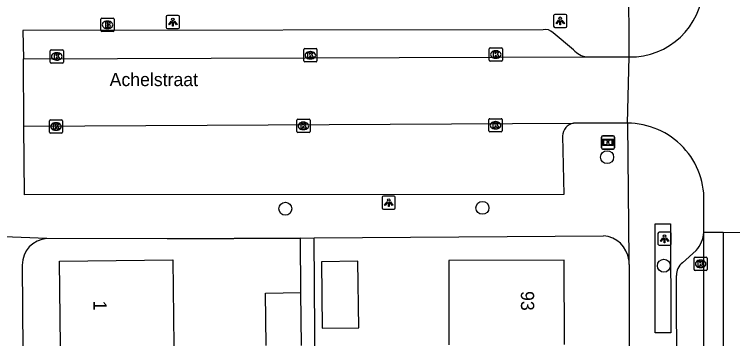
# Model space of a CAD drawing. Extents: x 160732 to 162105, y 387428 to 388479.
# Drawn here: x 161248.1 to 161302.4, y 388250.9 to 388275.4 of the extents above; entities that cross this region are included whole.
import ezdxf

# ---------------------------------------------------------------- set-up
doc = ezdxf.new("R2010")
doc.units = 0
for name, color, linetype in [('IMGEO_Boom', 7, 'Continuous'), ('IMGEO_Brandkraan', 7, 'Continuous'), ('IMGEO_Informatiebord', 7, 'Continuous'), ('IMGEO_Kolk', 7, 'Continuous'), ('IMGEO_Lichtpunt', 7, 'Continuous'), ('IMGEO_Muur', 7, 'Continuous'), ('IMGEO_Openbare_ruimte_label', 7, 'Continuous'), ('IMGEO_Pand', 7, 'Continuous'), ('IMGEO_Pand_nummerreeks', 7, 'Continuous'), ('IMGEO_Rijbaan_lokaal_gesloten', 7, 'Continuous'), ('IMGEO_Rijbaan_lokaal_open', 7, 'Continuous'), ('IMGEO_Voetpad_open', 7, 'Continuous')]:
    doc.layers.add(name, color=color, linetype=linetype)

msp = doc.modelspace()

# ---------------------------------------------------------------- linework, layer by layer
at = {"layer": 'IMGEO_Boom'}
for centre in [(161292.915, 388264.627), (161268.574, 388260.723), (161283.483, 388260.792), (161297.209, 388256.413)]:
    msp.add_circle(centre, 0.489, dxfattribs=at)
at = {"layer": 'IMGEO_Brandkraan'}
for p, q in [((161254.615, 388274.211), (161254.615, 388275.063)), ((161254.69, 388275.137), (161255.542, 388275.137)), ((161255.103, 388274.917), (161255.128, 388274.917)), ((161255.616, 388275.063), (161255.616, 388274.211)), ((161255.126, 388274.357), (161255.101, 388274.357)), ((161255.542, 388274.137), (161254.69, 388274.137))]:
    msp.add_line(p, q, dxfattribs=at)
for points in [[(161254.615, 388274.211), (161254.615, 388275.063)], [(161254.69, 388275.137), (161255.542, 388275.137)], [(161255.616, 388275.063), (161255.616, 388274.211)], [(161254.963, 388274.837), (161254.963, 388274.437), (161255.176, 388274.437)], [(161255.194, 388274.837), (161254.963, 388274.837)], [(161255.142, 388274.756), (161255.088, 388274.756), (161255.088, 388274.68)], [(161255.088, 388274.68), (161255.141, 388274.68)], [(161255.15, 388274.604), (161255.088, 388274.604), (161255.088, 388274.523)], [(161255.088, 388274.523), (161255.15, 388274.523)], [(161255.542, 388274.137), (161254.69, 388274.137)]]:
    msp.add_lwpolyline(points, dxfattribs=at)
for centre, radius, start, end in [((161254.692, 388275.061), 0.0765, 91.552, 178.448), ((161254.692, 388275.061), 0.0765, 91.552, 178.448), ((161255.54, 388275.061), 0.0765, 1.552, 88.448), ((161255.54, 388275.061), 0.0765, 1.552, 88.448), ((161255.143, 388274.718), 0.0379, 267.8285, 90.9355), ((161255.151, 388274.563), 0.0404, 269.8759, 90.5077), ((161255.182, 388274.688), 0.251, 268.6676, 293.5347), ((161255.198, 388274.692), 0.145, 59.4692, 91.5367), ((161255.223, 388274.739), 0.0922, 285.5137, 58.1501), ((161255.228, 388274.547), 0.105, 301.3115, 78.989), ((161254.692, 388274.213), 0.0765, 181.552, 268.448), ((161254.692, 388274.213), 0.0765, 181.552, 268.448), ((161255.54, 388274.213), 0.0765, 271.552, 358.448), ((161255.54, 388274.213), 0.0765, 271.552, 358.448)]:
    msp.add_arc(centre, radius, start, end, dxfattribs=at)
for centre, major_axis, ratio, start_param, end_param in [((161255.102, 388274.637), (-0.387, 0.002), 0.722429, 4.712389, 7.853982), ((161255.127, 388274.637), (-0.39, 0.002), 0.717154, 1.570796, 4.712389)]:
    msp.add_ellipse(centre, major_axis=major_axis, ratio=ratio, start_param=start_param, end_param=end_param, dxfattribs=at)
at = {"layer": 'IMGEO_Informatiebord'}
for p, q in [((161292.586, 388266.244), (161293.376, 388266.244)), ((161293.376, 388266.244), (161292.586, 388266.244)), ((161292.486, 388265.344), (161292.486, 388266.144)), ((161292.486, 388266.144), (161292.486, 388265.344)), ((161293.476, 388266.144), (161293.476, 388265.344)), ((161293.476, 388265.344), (161293.476, 388266.144)), ((161293.376, 388265.244), (161292.586, 388265.244)), ((161292.586, 388265.244), (161293.376, 388265.244))]:
    msp.add_line(p, q, dxfattribs=at)
for points in [[(161292.587, 388265.976), (161293.375, 388265.976), (161293.375, 388265.512), (161292.587, 388265.512), (161292.587, 388265.976)], [(161292.652, 388265.911), (161292.652, 388265.577), (161292.927, 388265.577), (161292.928, 388265.79), (161293.032, 388265.791), (161293.033, 388265.577), (161293.31, 388265.577), (161293.31, 388265.911), (161293.034, 388265.911), (161293.034, 388265.831), (161292.928, 388265.831), (161292.928, 388265.911), (161292.652, 388265.911)]]:
    msp.add_lwpolyline(points, dxfattribs=at)
for centre, start, end in [((161292.586, 388266.144), 90, 180), ((161292.586, 388266.144), 90, 180), ((161293.376, 388266.144), 0, 90), ((161293.376, 388266.144), 360, 90), ((161292.586, 388265.344), 180, 270), ((161292.586, 388265.344), 180, 270), ((161293.376, 388265.344), 270, 0), ((161293.376, 388265.344), 270, 0)]:
    msp.add_arc(centre, 0.1, start, end, dxfattribs=at)
at = {"layer": 'IMGEO_Kolk'}
for p, q in [((161250.853, 388272.746), (161251.705, 388272.746)), ((161269.964, 388271.909), (161269.964, 388272.761)), ((161270.039, 388272.835), (161270.891, 388272.835)), ((161270.965, 388272.761), (161270.965, 388271.909)), ((161283.995, 388271.963), (161283.995, 388272.815)), ((161284.07, 388272.889), (161284.922, 388272.889)), ((161284.996, 388272.815), (161284.996, 388271.963)), ((161250.778, 388271.82), (161250.778, 388272.672)), ((161251.266, 388272.526), (161251.291, 388272.526)), ((161251.779, 388272.672), (161251.779, 388271.82)), ((161270.452, 388272.615), (161270.477, 388272.615)), ((161284.483, 388272.669), (161284.508, 388272.669)), ((161251.705, 388271.746), (161250.853, 388271.746)), ((161251.289, 388271.966), (161251.264, 388271.966)), ((161270.891, 388271.835), (161270.039, 388271.835)), ((161270.475, 388272.055), (161270.45, 388272.055)), ((161284.922, 388271.889), (161284.07, 388271.889)), ((161284.506, 388272.109), (161284.481, 388272.109)), ((161250.719, 388266.519), (161250.719, 388267.371)), ((161250.794, 388267.445), (161251.646, 388267.445)), ((161251.72, 388267.371), (161251.72, 388266.519)), ((161269.438, 388266.566), (161269.438, 388267.418)), ((161269.513, 388267.492), (161270.365, 388267.492)), ((161269.926, 388267.272), (161269.951, 388267.272)), ((161270.439, 388267.418), (161270.439, 388266.566)), ((161283.976, 388266.612), (161283.976, 388267.464)), ((161284.051, 388267.538), (161284.903, 388267.538)), ((161284.464, 388267.318), (161284.489, 388267.318)), ((161284.977, 388267.464), (161284.977, 388266.612)), ((161251.207, 388267.225), (161251.232, 388267.225)), ((161284.487, 388266.758), (161284.462, 388266.758)), ((161251.646, 388266.445), (161250.794, 388266.445)), ((161251.23, 388266.665), (161251.205, 388266.665)), ((161270.365, 388266.492), (161269.513, 388266.492)), ((161269.949, 388266.712), (161269.924, 388266.712)), ((161284.903, 388266.538), (161284.051, 388266.538)), ((161299.491, 388256.129), (161299.491, 388256.981)), ((161299.566, 388257.055), (161300.418, 388257.055)), ((161300.492, 388256.981), (161300.492, 388256.129)), ((161299.979, 388256.835), (161300.004, 388256.835)), ((161300.418, 388256.055), (161299.566, 388256.055)), ((161300.002, 388256.275), (161299.977, 388256.275))]:
    msp.add_line(p, q, dxfattribs=at)
for points in [[(161250.853, 388272.746), (161251.705, 388272.746)], [(161269.964, 388271.909), (161269.964, 388272.761)], [(161270.039, 388272.835), (161270.891, 388272.835)], [(161270.965, 388272.761), (161270.965, 388271.909)], [(161283.995, 388271.963), (161283.995, 388272.815)], [(161284.07, 388272.889), (161284.922, 388272.889)], [(161284.996, 388272.815), (161284.996, 388271.963)], [(161250.778, 388271.82), (161250.778, 388272.672)], [(161251.099, 388272.446), (161251.222, 388272.446), (161251.222, 388272.295), (161251.352, 388272.446), (161251.516, 388272.446), (161251.37, 388272.295), (161251.523, 388272.046), (161251.371, 388272.046), (161251.286, 388272.21), (161251.222, 388272.143), (161251.222, 388272.046), (161251.099, 388272.046), (161251.099, 388272.446)], [(161251.779, 388272.672), (161251.779, 388271.82)], [(161270.285, 388272.535), (161270.408, 388272.535), (161270.408, 388272.384), (161270.538, 388272.535), (161270.702, 388272.535), (161270.556, 388272.384), (161270.709, 388272.135), (161270.557, 388272.135), (161270.472, 388272.299), (161270.408, 388272.232), (161270.408, 388272.135), (161270.285, 388272.135), (161270.285, 388272.535)], [(161284.316, 388272.589), (161284.439, 388272.589), (161284.439, 388272.438), (161284.569, 388272.589), (161284.733, 388272.589), (161284.587, 388272.438), (161284.74, 388272.189), (161284.588, 388272.189), (161284.503, 388272.353), (161284.439, 388272.286), (161284.439, 388272.189), (161284.316, 388272.189), (161284.316, 388272.589)], [(161251.705, 388271.746), (161250.853, 388271.746)], [(161270.891, 388271.835), (161270.039, 388271.835)], [(161284.922, 388271.889), (161284.07, 388271.889)], [(161250.719, 388266.519), (161250.719, 388267.371)], [(161250.794, 388267.445), (161251.646, 388267.445)], [(161251.72, 388267.371), (161251.72, 388266.519)], [(161269.438, 388266.566), (161269.438, 388267.418)], [(161269.513, 388267.492), (161270.365, 388267.492)], [(161270.439, 388267.418), (161270.439, 388266.566)], [(161283.976, 388266.612), (161283.976, 388267.464)], [(161284.051, 388267.538), (161284.903, 388267.538)], [(161284.977, 388267.464), (161284.977, 388266.612)], [(161251.04, 388267.145), (161251.163, 388267.145), (161251.163, 388266.994), (161251.293, 388267.145), (161251.457, 388267.145), (161251.311, 388266.994), (161251.464, 388266.745), (161251.312, 388266.745), (161251.227, 388266.909), (161251.163, 388266.842), (161251.163, 388266.745), (161251.04, 388266.745), (161251.04, 388267.145)], [(161269.759, 388267.192), (161269.882, 388267.192), (161269.882, 388267.041), (161270.012, 388267.192), (161270.176, 388267.192), (161270.03, 388267.041), (161270.183, 388266.792), (161270.031, 388266.792), (161269.946, 388266.956), (161269.882, 388266.889), (161269.882, 388266.792), (161269.759, 388266.792), (161269.759, 388267.192)], [(161284.297, 388267.238), (161284.42, 388267.238), (161284.42, 388267.087), (161284.55, 388267.238), (161284.714, 388267.238), (161284.568, 388267.087), (161284.721, 388266.838), (161284.569, 388266.838), (161284.484, 388267.002), (161284.42, 388266.935), (161284.42, 388266.838), (161284.297, 388266.838), (161284.297, 388267.238)], [(161251.646, 388266.445), (161250.794, 388266.445)], [(161270.365, 388266.492), (161269.513, 388266.492)], [(161284.903, 388266.538), (161284.051, 388266.538)], [(161299.491, 388256.129), (161299.491, 388256.981)], [(161299.566, 388257.055), (161300.418, 388257.055)], [(161300.492, 388256.981), (161300.492, 388256.129)], [(161299.812, 388256.755), (161299.935, 388256.755), (161299.935, 388256.604), (161300.065, 388256.755), (161300.229, 388256.755), (161300.083, 388256.604), (161300.236, 388256.355), (161300.084, 388256.355), (161299.999, 388256.519), (161299.935, 388256.452), (161299.935, 388256.355), (161299.812, 388256.355), (161299.812, 388256.755)], [(161300.418, 388256.055), (161299.566, 388256.055)]]:
    msp.add_lwpolyline(points, dxfattribs=at)
for centre, start, end in [((161250.855, 388272.67), 91.552, 178.448), ((161250.855, 388272.67), 91.552, 178.448), ((161251.703, 388272.67), 1.552, 88.448), ((161251.703, 388272.67), 1.552, 88.448), ((161270.041, 388272.759), 91.552, 178.448), ((161270.041, 388272.759), 91.552, 178.448), ((161270.889, 388272.759), 1.552, 88.448), ((161270.889, 388272.759), 1.552, 88.448), ((161284.072, 388272.813), 91.552, 178.448), ((161284.072, 388272.813), 91.552, 178.448), ((161284.92, 388272.813), 1.552, 88.448), ((161284.92, 388272.813), 1.552, 88.448), ((161250.855, 388271.822), 181.552, 268.448), ((161250.855, 388271.822), 181.552, 268.448), ((161251.703, 388271.822), 271.552, 358.448), ((161251.703, 388271.822), 271.552, 358.448), ((161270.041, 388271.911), 181.552, 268.448), ((161270.041, 388271.911), 181.552, 268.448), ((161270.889, 388271.911), 271.552, 358.448), ((161270.889, 388271.911), 271.552, 358.448), ((161284.072, 388271.965), 181.552, 268.448), ((161284.072, 388271.965), 181.552, 268.448), ((161284.92, 388271.965), 271.552, 358.448), ((161284.92, 388271.965), 271.552, 358.448), ((161250.796, 388267.369), 91.552, 178.448), ((161250.796, 388267.369), 91.552, 178.448), ((161251.644, 388267.369), 1.552, 88.448), ((161251.644, 388267.369), 1.552, 88.448), ((161269.515, 388267.416), 91.552, 178.448), ((161269.515, 388267.416), 91.552, 178.448), ((161270.363, 388267.416), 1.552, 88.448), ((161270.363, 388267.416), 1.552, 88.448), ((161284.053, 388267.462), 91.552, 178.448), ((161284.053, 388267.462), 91.552, 178.448), ((161284.901, 388267.462), 1.552, 88.448), ((161284.901, 388267.462), 1.552, 88.448), ((161250.796, 388266.521), 181.552, 268.448), ((161250.796, 388266.521), 181.552, 268.448), ((161251.644, 388266.521), 271.552, 358.448), ((161251.644, 388266.521), 271.552, 358.448), ((161269.515, 388266.568), 181.552, 268.448), ((161269.515, 388266.568), 181.552, 268.448), ((161270.363, 388266.568), 271.552, 358.448), ((161270.363, 388266.568), 271.552, 358.448), ((161284.053, 388266.614), 181.552, 268.448), ((161284.053, 388266.614), 181.552, 268.448), ((161284.901, 388266.614), 271.552, 358.448), ((161284.901, 388266.614), 271.552, 358.448), ((161299.568, 388256.979), 91.552, 178.448), ((161299.568, 388256.979), 91.552, 178.448), ((161300.416, 388256.979), 1.552, 88.448), ((161300.416, 388256.979), 1.552, 88.448), ((161299.568, 388256.131), 181.552, 268.448), ((161299.568, 388256.131), 181.552, 268.448), ((161300.416, 388256.131), 271.552, 358.448), ((161300.416, 388256.131), 271.552, 358.448)]:
    msp.add_arc(centre, 0.0765, start, end, dxfattribs=at)
for centre, major_axis, ratio, start_param, end_param in [((161251.265, 388272.246), (-0.387, 0.002), 0.722429, 4.712389, 7.853982), ((161251.29, 388272.246), (-0.39, 0.002), 0.717154, 1.570796, 4.712389), ((161270.451, 388272.335), (-0.387, 0.002), 0.722429, 4.712389, 7.853982), ((161270.476, 388272.335), (-0.39, 0.002), 0.717154, 1.570796, 4.712389), ((161284.482, 388272.389), (-0.387, 0.002), 0.722429, 4.712389, 7.853982), ((161284.507, 388272.389), (-0.39, 0.002), 0.717154, 1.570796, 4.712389), ((161269.925, 388266.992), (-0.387, 0.002), 0.722429, 4.712389, 7.853982), ((161269.95, 388266.992), (-0.39, 0.002), 0.717154, 1.570796, 4.712389), ((161284.463, 388267.038), (-0.387, 0.002), 0.722429, 4.712389, 7.853982), ((161284.488, 388267.038), (-0.39, 0.002), 0.717154, 1.570796, 4.712389), ((161251.206, 388266.945), (-0.387, 0.002), 0.722429, 4.712389, 7.853982), ((161251.231, 388266.945), (-0.39, 0.002), 0.717154, 1.570796, 4.712389), ((161299.978, 388256.555), (-0.387, 0.002), 0.722429, 4.712389, 7.853982), ((161300.003, 388256.555), (-0.39, 0.002), 0.717154, 1.570796, 4.712389)]:
    msp.add_ellipse(centre, major_axis=major_axis, ratio=ratio, start_param=start_param, end_param=end_param, dxfattribs=at)
at = {"layer": 'IMGEO_Lichtpunt'}
for p, q in [((161289.773, 388275.428), (161288.965, 388275.428)), ((161289.773, 388275.428), (161288.965, 388275.428)), ((161259.566, 388275.252), (161259.566, 388274.445)), ((161259.566, 388275.252), (161259.566, 388274.445)), ((161260.468, 388275.347), (161259.66, 388275.347)), ((161260.468, 388275.347), (161259.66, 388275.347)), ((161260.562, 388274.445), (161260.562, 388275.252)), ((161260.562, 388274.445), (161260.562, 388275.252)), ((161288.871, 388275.333), (161288.871, 388274.526)), ((161288.871, 388275.333), (161288.871, 388274.526)), ((161289.867, 388274.526), (161289.867, 388275.333)), ((161289.867, 388274.526), (161289.867, 388275.333)), ((161259.66, 388274.351), (161260.468, 388274.351)), ((161259.66, 388274.351), (161260.468, 388274.351)), ((161288.965, 388274.432), (161289.773, 388274.432)), ((161288.965, 388274.432), (161289.773, 388274.432)), ((161275.892, 388261.589), (161275.892, 388260.782)), ((161275.892, 388261.589), (161275.892, 388260.782)), ((161276.794, 388261.684), (161275.986, 388261.684)), ((161276.794, 388261.684), (161275.986, 388261.684)), ((161276.888, 388260.782), (161276.888, 388261.589)), ((161276.888, 388260.782), (161276.888, 388261.589)), ((161275.986, 388260.688), (161276.794, 388260.688)), ((161275.986, 388260.688), (161276.794, 388260.688)), ((161296.764, 388258.864), (161296.764, 388258.057)), ((161296.764, 388258.864), (161296.764, 388258.057)), ((161297.666, 388258.959), (161296.858, 388258.959)), ((161297.666, 388258.959), (161296.858, 388258.959)), ((161297.76, 388258.057), (161297.76, 388258.864)), ((161297.76, 388258.057), (161297.76, 388258.864)), ((161296.858, 388257.963), (161297.666, 388257.963)), ((161296.858, 388257.963), (161297.666, 388257.963))]:
    msp.add_line(p, q, dxfattribs=at)
for points in [[(161259.94, 388274.916), (161259.979, 388274.888), (161259.791, 388274.626), (161259.753, 388274.653), (161259.94, 388274.916)], [(161260.152, 388274.888), (161260.19, 388274.915), (161260.377, 388274.653), (161260.338, 388274.625), (161260.152, 388274.888)], [(161289.245, 388274.997), (161289.284, 388274.969), (161289.096, 388274.707), (161289.058, 388274.734), (161289.245, 388274.997)], [(161289.347, 388274.949), (161289.394, 388274.949), (161289.394, 388274.627), (161289.347, 388274.627), (161289.347, 388274.949)], [(161289.457, 388274.969), (161289.495, 388274.996), (161289.682, 388274.734), (161289.643, 388274.706), (161289.457, 388274.969)], [(161260.042, 388274.868), (161260.089, 388274.868), (161260.089, 388274.546), (161260.042, 388274.546), (161260.042, 388274.868)], [(161276.266, 388261.253), (161276.305, 388261.225), (161276.117, 388260.963), (161276.079, 388260.99), (161276.266, 388261.253)], [(161276.368, 388261.205), (161276.415, 388261.205), (161276.415, 388260.883), (161276.368, 388260.883), (161276.368, 388261.205)], [(161276.478, 388261.225), (161276.516, 388261.252), (161276.703, 388260.99), (161276.664, 388260.962), (161276.478, 388261.225)], [(161297.138, 388258.528), (161297.177, 388258.5), (161296.989, 388258.238), (161296.951, 388258.265), (161297.138, 388258.528)], [(161297.24, 388258.48), (161297.287, 388258.48), (161297.287, 388258.158), (161297.24, 388258.158), (161297.24, 388258.48)], [(161297.35, 388258.5), (161297.388, 388258.527), (161297.575, 388258.265), (161297.536, 388258.237), (161297.35, 388258.5)]]:
    msp.add_lwpolyline(points, dxfattribs=at)
for centre in [(161260.065, 388275.05), (161289.37, 388275.131), (161276.391, 388261.387), (161297.263, 388258.662)]:
    msp.add_circle(centre, 0.0994, dxfattribs=at)
for centre, start, end in [((161288.965, 388275.333), 90, 180), ((161288.965, 388275.333), 90, 180), ((161289.773, 388275.333), 0, 90), ((161289.773, 388275.333), 0, 90), ((161259.66, 388275.252), 90, 180), ((161259.66, 388275.252), 90, 180), ((161260.468, 388275.252), 0, 90), ((161260.468, 388275.252), 0, 90), ((161259.66, 388274.445), 180, 270), ((161259.66, 388274.445), 180, 270), ((161260.468, 388274.445), 270, 0), ((161260.468, 388274.445), 270, 360), ((161288.965, 388274.526), 180, 270), ((161288.965, 388274.526), 180, 270), ((161289.773, 388274.526), 270, 0), ((161289.773, 388274.526), 270, 360), ((161275.986, 388261.589), 90, 180), ((161275.986, 388261.589), 90, 180), ((161276.794, 388261.589), 0, 90), ((161276.794, 388261.589), 0, 90), ((161275.986, 388260.782), 180, 270), ((161275.986, 388260.782), 180, 270), ((161276.794, 388260.782), 270, 0), ((161276.794, 388260.782), 270, 360), ((161296.858, 388258.864), 90, 180), ((161296.858, 388258.864), 90, 180), ((161297.666, 388258.864), 0, 90), ((161297.666, 388258.864), 0, 90), ((161296.858, 388258.057), 180, 270), ((161296.858, 388258.057), 180, 270), ((161297.666, 388258.057), 270, 0), ((161297.666, 388258.057), 270, 360)]:
    msp.add_arc(centre, 0.0946, start, end, dxfattribs=at)
at = {"layer": 'IMGEO_Muur'}
msp.add_lwpolyline([(161259.658, 388258.461), (161269.715, 388258.507)], dxfattribs=at)
at = {"layer": 'IMGEO_Pand'}
for points in [[(161251.567, 388250.329), (161251.496, 388256.761), (161260.057, 388256.856), (161260.13, 388250.356)], [(161274.125, 388251.72), (161274.064, 388256.75), (161271.305, 388256.717), (161271.367, 388251.686), (161274.125, 388251.72)], [(161289.686, 388250.45), (161289.666, 388256.842), (161280.932, 388256.814), (161280.952, 388250.422)], [(161267.116, 388250.378), (161267.063, 388254.348), (161269.731, 388254.384)], [(161269.784, 388250.386), (161269.731, 388254.384)]]:
    msp.add_lwpolyline(points, dxfattribs=at)
at = {"layer": 'IMGEO_Rijbaan_lokaal_gesloten'}
for points in [[(161300.242, 388258.948), (161301.703, 388258.945)], [(161300.288, 388211.931), (161300.242, 388258.948)], [(161301.703, 388258.945), (161301.703, 388232.778)], [(161301.703, 388258.945), (161305.21, 388258.937)]]:
    msp.add_lwpolyline(points, dxfattribs=at)
at = {"layer": 'IMGEO_Rijbaan_lokaal_open'}
for points in [[(161248.773, 388272.059), (161291.387, 388272.22)], [(161291.387, 388272.22), (161294.582, 388272.207)], [(161294.452, 388267.196), (161294.582, 388272.207)], [(161248.779, 388266.979), (161248.773, 388272.059)], [(161248.779, 388266.979), (161290.368, 388267.21)], [(161294.452, 388267.196), (161290.368, 388267.21)], [(161300.242, 388258.948), (161300.228, 388261.023)]]:
    msp.add_lwpolyline(points, dxfattribs=at)
for centre, radius, start, end in [((161294.678, 388277.722), 5.516, 269.0057, 357.6617), ((161294.465, 388261.419), 5.777, 356.0694, 90.1248)]:
    msp.add_arc(centre, radius, start, end, dxfattribs=at)
at = {"layer": 'IMGEO_Voetpad_open'}
for points in [[(161294.582, 388272.207), (161294.569, 388278.198), (161294.566, 388278.247)], [(161288.08, 388274.267), (161248.709, 388274.21), (161248.773, 388272.059)], [(161290.382, 388272.745), (161288.83, 388274.04)], [(161289.547, 388266.228), (161289.64, 388261.79), (161248.833, 388261.778), (161248.779, 388266.979)], [(161294.452, 388267.196), (161294.562, 388256.871)], [(161296.549, 388251.35), (161296.545, 388259.579), (161297.72, 388259.58), (161297.724, 388251.351), (161296.549, 388251.35)], [(161250.531, 388258.473), (161244.029, 388258.736), (161243.841, 388258.72)], [(161270.747, 388258.514), (161292.647, 388258.673)], [(161269.715, 388258.507), (161259.658, 388258.461), (161250.531, 388258.473)], [(161269.715, 388258.507), (161270.747, 388258.514)], [(161269.731, 388254.384), (161269.715, 388258.507)], [(161271.491, 388212.388), (161271.081, 388212.385), (161270.747, 388258.514)], [(161298.62, 388256.642), (161299.654, 388257.575)], [(161248.664, 388256.463), (161248.844, 388233.81)], [(161294.581, 388256.5), (161294.668, 388212.623)], [(161298.288, 388215.143), (161298.169, 388255.676)]]:
    msp.add_lwpolyline(points, dxfattribs=at)
for centre, radius, start, end in [((161288.239, 388273.44), 0.843, 45.4477, 100.8737), ((161291.523, 388273.704), 1.49, 220.0605, 264.7755), ((161290.568, 388266.208), 1.021, 101.3076, 178.8978), ((161292.482, 388256.579), 2.101, 7.9941, 85.4885), ((161297.973, 388259.107), 2.274, 317.6453, 355.9878), ((161250.673, 388256.469), 2.009, 94.0655, 180.1592), ((161292.552, 388256.582), 2.03, 357.6825, 8.1809), ((161299.286, 388255.743), 1.119, 126.5269, 183.4199)]:
    msp.add_arc(centre, radius, start, end, dxfattribs=at)

# ---------------------------------------------------------------- texts
at = {"layer": 'IMGEO_Openbare_ruimte_label'}
msp.add_text('Achelstraat', height=1, dxfattribs=at).set_placement((161255.278, 388270))
at = {"layer": 'IMGEO_Pand_nummerreeks'}
for s, rotation, p in [('93', 270.18, (161286.393, 388254.498)), ('1', 270.6393, (161254.049, 388253.77))]:
    msp.add_text(s, height=1, rotation=rotation, dxfattribs=at).set_placement(p)

doc.saveas('drawing.dxf')
